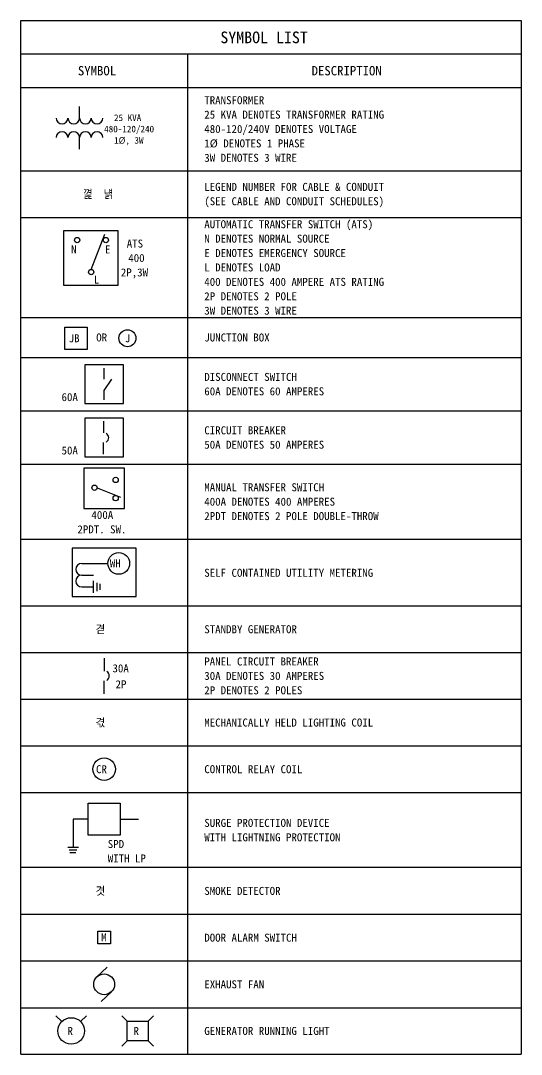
# Model space of a CAD drawing. Extents: x 0 to 0.63, y 0 to 1.29.
import ezdxf

# ---------------------------------------------------------------- set-up
doc = ezdxf.new("R2010")
doc.units = 0
for name, color, linetype in [('HS_Dimensions_and_Text', 7, 'Continuous'), ('HS_Electrical_Devices', 7, 'Continuous'), ('HS_Table_Border', 7, 'Continuous'), ('HS_Table_Lines', 7, 'Continuous')]:
    doc.layers.add(name, color=color, linetype=linetype)

msp = doc.modelspace()

# ---------------------------------------------------------------- linework, layer by layer
at = {"layer": 'HS_Electrical_Devices'}
for p, q in [((0.0735, 1.17), (0.0735, 1.1845)), ((0.0735, 1.1311), (0.0735, 1.1456)), ((0.088, 0.9808), (0.105, 1.0249)), ((0.1041, 0.8438), (0.1041, 0.8575)), ((0.1041, 0.8296), (0.1139, 0.8435)), ((0.1041, 0.8178), (0.1041, 0.8296)), ((0.1034, 0.7913), (0.1034, 0.7768)), ((0.1034, 0.7498), (0.1034, 0.7644)), ((0.0954, 0.708), (0.1245, 0.6963)), ((0.0762, 0.6135), (0.1088, 0.6135)), ((0.0762, 0.5988), (0.0909, 0.5988)), ((0.0762, 0.5841), (0.0909, 0.5841)), ((0.0909, 0.5765), (0.0909, 0.5917)), ((0.0955, 0.5789), (0.0955, 0.5893)), ((0.0993, 0.5806), (0.0993, 0.5881)), ((0.1042, 0.4951), (0.1042, 0.4789)), ((0.1042, 0.4505), (0.1042, 0.4667)), ((0.124, 0.2939), (0.1472, 0.2939)), ((0.0722, 0.2586), (0.0589, 0.2586)), ((0.0701, 0.2551), (0.0605, 0.2551)), ((0.0687, 0.2517), (0.0614, 0.2517)), ((0.0946, 0.0963), (0.108, 0.1089)), ((0.1137, 0.0787), (0.1003, 0.0661)), ((0.0513, 0.0409), (0.0439, 0.0483)), ((0.0748, 0.0409), (0.0822, 0.0483)), ((0.1329, 0.0416), (0.1262, 0.0483)), ((0.1591, 0.0416), (0.1659, 0.0483)), ((0.1262, 0.01), (0.1329, 0.0167)), ((0.1659, 0.01), (0.1591, 0.0167))]:
    msp.add_line(p, q, dxfattribs=at)
for points in [[(0.1215, 1.0291), (0.0535, 1.0291), (0.0535, 0.9611), (0.1215, 0.9611)], [(0.055, 0.9088), (0.0831, 0.9088), (0.0831, 0.8807), (0.055, 0.8807)], [(0.1283, 0.8134), (0.1283, 0.8616), (0.0801, 0.8616), (0.0801, 0.8134)], [(0.1283, 0.7467), (0.1283, 0.7949), (0.0801, 0.7949), (0.0801, 0.7467)], [(0.1294, 0.6819), (0.1294, 0.7324), (0.0789, 0.7324), (0.0789, 0.6819)], [(0.1442, 0.6323), (0.0642, 0.6323), (0.0642, 0.5719), (0.1442, 0.5719)], [(0.0843, 0.274), (0.0843, 0.3137), (0.124, 0.3137), (0.124, 0.274)], [(0.0963, 0.1537), (0.112, 0.1537), (0.112, 0.138), (0.0963, 0.138)], [(0.1329, 0.0416), (0.1591, 0.0416), (0.1591, 0.0167), (0.1329, 0.0167)]]:
    msp.add_lwpolyline(points, close=True, dxfattribs=at)
msp.add_lwpolyline([(0.0843, 0.2939), (0.0656, 0.2939), (0.0656, 0.2586)], dxfattribs=at)
for centre, radius in [((0.0705, 1.0175), 0.00329), ((0.1063, 1.0175), 0.00329), ((0.088, 0.9775), 0.00329), ((0.1333, 0.8948), 0.0106), ((0.0922, 0.708), 0.00329), ((0.1186, 0.7178), 0.00329), ((0.1186, 0.695), 0.00329), ((0.1224, 0.6135), 0.0136), ((0.1042, 0.3563), 0.0141), ((0.1042, 0.0875), 0.013), ((0.0631, 0.0292), 0.0166)]:
    msp.add_circle(centre, radius, dxfattribs=at)
for centre, radius, start, end in [((0.0516, 1.17), 0.00729, 180, 360), ((0.0662, 1.17), 0.00729, 180, 360), ((0.0808, 1.17), 0.00729, 180, 360), ((0.0953, 1.17), 0.00729, 180, 360), ((0.0516, 1.1456), 0.00729, 360, 180), ((0.0662, 1.1456), 0.00729, 360, 180), ((0.0808, 1.1456), 0.00729, 360, 180), ((0.0953, 1.1456), 0.00729, 360, 180), ((0.1034, 0.7706), 0.00645, 300.4763, 60.1754), ((0.0762, 0.6061), 0.00735, 90, 270), ((0.0762, 0.5914), 0.00735, 90, 270), ((0.1042, 0.4729), 0.00645, 300.4763, 60.1754)]:
    msp.add_arc(centre, radius, start, end, dxfattribs=at)
at = {"layer": 'HS_Table_Border'}
for p, q in [((0, 1.2917), (0.625, 1.2917)), ((0, 0), (0, 1.2917)), ((0.625, 1.2917), (0.625, 0)), ((0.625, 1.25), (0, 1.25)), ((0, 0), (0.625, 0))]:
    msp.add_line(p, q, dxfattribs=at)
at = {"layer": 'HS_Table_Lines'}
for p, q in [((0.2083, 1.2496), (0.2083, 0)), ((0, 1.2083), (0.625, 1.2083)), ((0.0005, 1.1042), (0.625, 1.1042)), ((0, 1.0458), (0.625, 1.0458)), ((0, 0.9208), (0.625, 0.9208)), ((0, 0.8708), (0.625, 0.8708)), ((0, 0.8042), (0.625, 0.8042)), ((0, 0.7375), (0.625, 0.7375)), ((0, 0.6438), (0.625, 0.6438)), ((0, 0.5604), (0.625, 0.5604)), ((0, 0.5021), (0.625, 0.5021)), ((0, 0.4437), (0.625, 0.4437)), ((0, 0.3854), (0.625, 0.3854)), ((0, 0.3271), (0.625, 0.3271)), ((0.625, 0.2333), (0, 0.2333)), ((0, 0.175), (0.625, 0.175)), ((0, 0.1167), (0.625, 0.1167)), ((0, 0.0583), (0.625, 0.0583))]:
    msp.add_line(p, q, dxfattribs=at)

# ---------------------------------------------------------------- texts
at = {"layer": 'HS_Dimensions_and_Text'}
for s, height, rotation, p in [('SYMBOL LIST', 0.014583, 360, (0.2493, 1.2635)), ('SYMBOL', 0.0117, 360, (0.0714, 1.2233)), ('DESCRIPTION', 0.0117, 360, (0.3632, 1.2233)), ('TRANSFORMER', 0.01, 360, (0.2292, 1.1873)), ('25 KVA DENOTES TRANSFORMER RATING', 0.01, 360, (0.2292, 1.1693)), ('25 KVA', 0.00833, 360, (0.1165, 1.1662)), ('480-120/240', 0.008333, 360, (0.1042, 1.1521)), ('480-120/240V DENOTES VOLTAGE', 0.01, 360, (0.2292, 1.1513)), ('1Ø, 3W', 0.00833, 360, (0.1166, 1.1379)), ('1Ø DENOTES 1 PHASE', 0.01, 360, (0.2292, 1.1333)), ('3W DENOTES 3 WIRE', 0.01, 360, (0.2292, 1.1153)), ('LEGEND NUMBER FOR CABLE & CONDUIT', 0.01, 360, (0.2292, 1.079)), ('꼁  냵', 0.01, 0, (0.078, 1.07)), ('(SEE CABLE AND CONDUIT SCHEDULES)', 0.01, 360, (0.2292, 1.061)), ('AUTOMATIC TRANSFER SWITCH (ATS)', 0.01, 360, (0.2292, 1.0323)), ('N DENOTES NORMAL SOURCE', 0.01, 360, (0.2292, 1.0143)), ('N', 0.01, 360, (0.063, 1.0008)), ('E', 0.01, 360, (0.1052, 1.0008)), ('ATS', 0.01, 360, (0.1324, 1.0081)), ('400', 0.01, 360, (0.1343, 0.9901)), ('E DENOTES EMERGENCY SOURCE', 0.01, 360, (0.2292, 0.9963)), ('2P,3W', 0.01, 360, (0.125, 0.9721)), ('L DENOTES LOAD', 0.01, 360, (0.2292, 0.9783)), ('L', 0.01, 360, (0.0914, 0.9631)), ('400 DENOTES 400 AMPERE ATS RATING', 0.01, 360, (0.2292, 0.9603)), ('2P DENOTES 2 POLE', 0.01, 360, (0.2292, 0.9423)), ('3W DENOTES 3 WIRE', 0.01, 360, (0.2292, 0.9243)), ('JB', 0.01, 360, (0.0599, 0.8898)), ('OR', 0.01, 360, (0.0943, 0.8908)), ('J', 0.01, 360, (0.1301, 0.8898)), ('JUNCTION BOX', 0.01, 360, (0.2292, 0.8908)), ('DISCONNECT SWITCH', 0.01, 360, (0.2292, 0.8415)), ('60A DENOTES 60 AMPERES', 0.01, 360, (0.2292, 0.8235)), ('60A', 0.01, 360, (0.051, 0.8163)), ('CIRCUIT BREAKER', 0.01, 360, (0.2292, 0.7748)), ('50A DENOTES 50 AMPERES', 0.01, 360, (0.2292, 0.7568)), ('50A', 0.01, 360, (0.051, 0.7496)), ('MANUAL TRANSFER SWITCH', 0.01, 360, (0.2292, 0.7036)), ('400A DENOTES 400 AMPERES', 0.01, 360, (0.2292, 0.6856)), ('400A', 0.01, 360, (0.0883, 0.669)), ('2PDT DENOTES 2 POLE DOUBLE-THROW', 0.01, 360, (0.2292, 0.6676)), ('2PDT. SW.', 0.01, 360, (0.0708, 0.651)), ('WH', 0.01, 360, (0.1113, 0.6085)), ('SELF CONTAINED UTILITY METERING', 0.01, 360, (0.2292, 0.5967)), ('겯', 0.01, 360, (0.0935, 0.5262)), ('STANDBY GENERATOR', 0.01, 360, (0.2292, 0.5262)), ('PANEL CIRCUIT BREAKER', 0.01, 360, (0.2292, 0.4859)), ('30A', 0.01, 360, (0.1146, 0.4774)), ('30A DENOTES 30 AMPERES', 0.01, 360, (0.2292, 0.4679)), ('2P', 0.01, 360, (0.1184, 0.4574)), ('2P DENOTES 2 POLES', 0.01, 360, (0.2292, 0.4499)), ('겫', 0.01, 360, (0.0935, 0.4096)), ('MECHANICALLY HELD LIGHTING COIL', 0.01, 360, (0.2292, 0.4096)), ('CR', 0.01, 360, (0.094, 0.3513)), ('CONTROL RELAY COIL', 0.01, 360, (0.2292, 0.3513)), ('SURGE PROTECTION DEVICE', 0.01, 360, (0.2292, 0.2842)), ('WITH LIGHTNING PROTECTION', 0.01, 360, (0.2292, 0.2662)), ('SPD', 0.01, 360, (0.1087, 0.2578)), ('WITH LP', 0.01, 360, (0.1087, 0.2398)), ('겻', 0.01, 360, (0.0935, 0.1992)), ('SMOKE DETECTOR', 0.01, 360, (0.2292, 0.1992)), ('DOOR ALARM SWITCH', 0.01, 360, (0.2292, 0.1408)), ('EXHAUST FAN', 0.01, 360, (0.2292, 0.0825)), ('R', 0.01, 0, (0.0584, 0.0242)), ('R', 0.01, 0, (0.1408, 0.0242)), ('GENERATOR RUNNING LIGHT', 0.01, 360, (0.2292, 0.0242))]:
    msp.add_text(s, height=height, rotation=rotation, dxfattribs=at).set_placement(p)
at = {"layer": 'HS_Electrical_Devices'}
msp.add_text('M', height=0.00991, rotation=360, dxfattribs=at).set_placement((0.1005, 0.1411))

doc.saveas('drawing.dxf')
